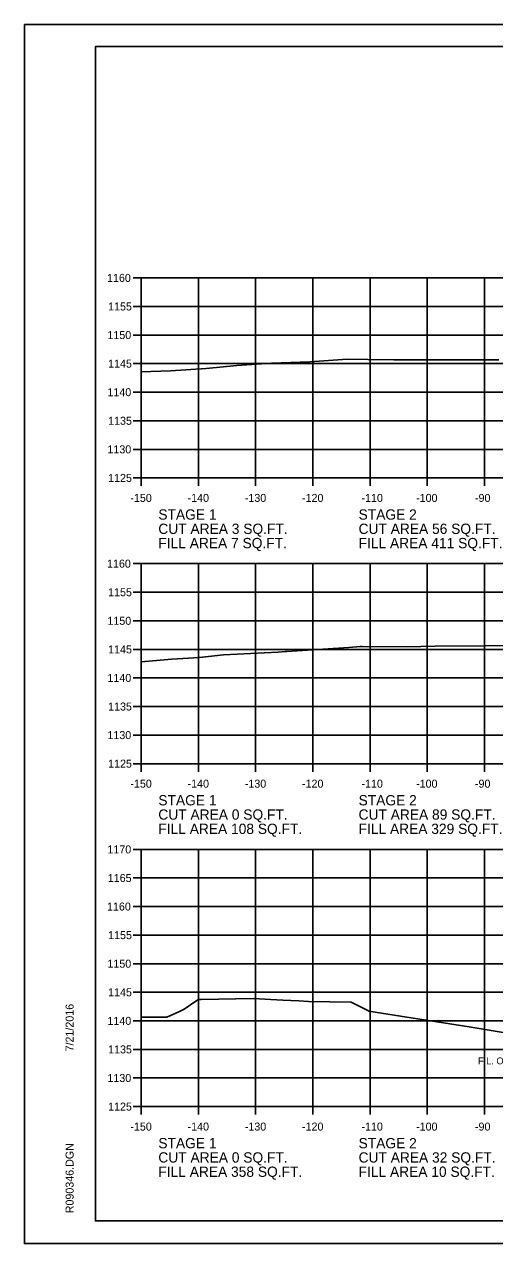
# Model space of a CAD drawing. Extents: x 1368971 to 1374497, y 378717 to 381839.
# Drawn here: x 1370882.3 to 1370964.5, y 379570.4 to 379783.8 of the extents above; entities that cross this region are included whole.
import ezdxf

# ---------------------------------------------------------------- set-up
doc = ezdxf.new("R2010")
doc.units = 0
for name, color, linetype in [('R_Axis', 7, 'Continuous'), ('R_Axis Annot', 7, 'Continuous'), ('R_Border', 7, 'Continuous'), ('R_Border Notes', 7, 'Continuous'), ('R_Exist Surface', 7, 'Continuous'), ('R_Grid', 7, 'Continuous'), ('R_No Plot', 7, 'Continuous')]:
    doc.layers.add(name, color=color, linetype=linetype)

msp = doc.modelspace()

# ---------------------------------------------------------------- linework, layer by layer
at = {"layer": 'R_Axis'}
for p, q in [((1370901.31, 379739.41), (1370902.71, 379739.41)), ((1370902.71, 379704.41), (1370902.71, 379739.41)), ((1370901.31, 379734.41), (1370902.71, 379734.41)), ((1370901.31, 379729.41), (1370902.71, 379729.41)), ((1370901.31, 379724.41), (1370902.71, 379724.41)), ((1370901.31, 379719.41), (1370902.71, 379719.41)), ((1370901.31, 379714.41), (1370902.71, 379714.41)), ((1370901.31, 379709.41), (1370902.71, 379709.41)), ((1370901.31, 379704.41), (1370902.71, 379704.41)), ((1370902.71, 379704.41), (1371202.71, 379704.41)), ((1370902.71, 379703.01), (1370902.71, 379704.41)), ((1370912.71, 379703.01), (1370912.71, 379704.41)), ((1370922.71, 379703.01), (1370922.71, 379704.41)), ((1370932.71, 379703.01), (1370932.71, 379704.41)), ((1370942.71, 379703.01), (1370942.71, 379704.41)), ((1370952.71, 379703.01), (1370952.71, 379704.41)), ((1370962.71, 379703.01), (1370962.71, 379704.41)), ((1370901.31, 379689.41), (1370902.71, 379689.41)), ((1370902.71, 379654.41), (1370902.71, 379689.41)), ((1370901.31, 379684.41), (1370902.71, 379684.41)), ((1370901.31, 379679.41), (1370902.71, 379679.41)), ((1370901.31, 379674.41), (1370902.71, 379674.41)), ((1370901.31, 379669.41), (1370902.71, 379669.41)), ((1370901.31, 379664.41), (1370902.71, 379664.41)), ((1370901.31, 379659.41), (1370902.71, 379659.41)), ((1370901.31, 379654.41), (1370902.71, 379654.41)), ((1370902.71, 379654.41), (1371202.71, 379654.41)), ((1370902.71, 379653.01), (1370902.71, 379654.41)), ((1370912.71, 379653.01), (1370912.71, 379654.41)), ((1370922.71, 379653.01), (1370922.71, 379654.41)), ((1370932.71, 379653.01), (1370932.71, 379654.41)), ((1370942.71, 379653.01), (1370942.71, 379654.41)), ((1370952.71, 379653.01), (1370952.71, 379654.41)), ((1370962.71, 379653.01), (1370962.71, 379654.41)), ((1370901.31, 379639.41), (1370902.71, 379639.41)), ((1370902.71, 379594.41), (1370902.71, 379639.41)), ((1370901.31, 379634.41), (1370902.71, 379634.41)), ((1370901.31, 379629.41), (1370902.71, 379629.41)), ((1370901.31, 379624.41), (1370902.71, 379624.41)), ((1370901.31, 379619.41), (1370902.71, 379619.41)), ((1370901.31, 379614.41), (1370902.71, 379614.41)), ((1370901.31, 379609.41), (1370902.71, 379609.41)), ((1370901.31, 379604.41), (1370902.71, 379604.41)), ((1370901.31, 379599.41), (1370902.71, 379599.41)), ((1370901.31, 379594.41), (1370902.71, 379594.41)), ((1370902.71, 379594.41), (1371202.71, 379594.41)), ((1370902.71, 379593.01), (1370902.71, 379594.41)), ((1370912.71, 379593.01), (1370912.71, 379594.41)), ((1370922.71, 379593.01), (1370922.71, 379594.41)), ((1370932.71, 379593.01), (1370932.71, 379594.41)), ((1370942.71, 379593.01), (1370942.71, 379594.41)), ((1370952.71, 379593.01), (1370952.71, 379594.41)), ((1370962.71, 379593.01), (1370962.71, 379594.41))]:
    msp.add_line(p, q, dxfattribs=at)
at = {"layer": 'R_Border'}
for p, q in [((1370894.71, 379779.87), (1371210.89, 379779.87)), ((1370894.71, 379574.41), (1370894.71, 379779.87)), ((1370894.71, 379574.41), (1370894.71, 379574.41)), ((1371210.89, 379574.41), (1370894.71, 379574.41))]:
    msp.add_line(p, q, dxfattribs=at)
at = {"layer": 'R_Exist Surface'}
for points in [[(1370902.71, 379722.95), (1370907.83, 379723.15), (1370914.06, 379723.56), (1370919.4, 379724.07), (1370925.49, 379724.49), (1370932.19, 379724.73), (1370938.7, 379725.2), (1370942.34, 379725.12), (1370946.87, 379725.09), (1370959.76, 379725.07), (1370962.04, 379725.08), (1370965.21, 379725.07)], [(1370902.71, 379672.21), (1370903.32, 379672.27), (1370908.07, 379672.67), (1370912.89, 379673), (1370917.1, 379673.46), (1370926.65, 379673.94), (1370927.86, 379674.03), (1370928.19, 379674.04), (1370930.85, 379674.23), (1370938.99, 379674.72), (1370940.96, 379674.92), (1370941.31, 379674.93), (1370949.06, 379674.88), (1370954.07, 379674.96), (1370962.9, 379675.03), (1370975.31, 379675.11)], [(1370902.71, 379610.03), (1370903.28, 379610.03), (1370907.17, 379610.04), (1370909.4, 379611.02), (1370910.2, 379611.43), (1370912.41, 379612.99), (1370912.72, 379613.14), (1370913.2, 379613.17), (1370922.31, 379613.32), (1370927.46, 379613.04), (1370930.27, 379612.9), (1370931.94, 379612.8), (1370939.41, 379612.67), (1370942.31, 379611.24), (1370942.48, 379611.11), (1370949.15, 379610.03), (1370960.06, 379608.36), (1370973.59, 379606.1)]]:
    msp.add_lwpolyline(points, dxfattribs=at)
at = {"layer": 'R_Grid'}
for p, q in [((1370902.71, 379739.41), (1371202.71, 379739.41)), ((1370902.71, 379704.41), (1370902.71, 379739.41)), ((1370912.71, 379704.41), (1370912.71, 379739.41)), ((1370922.71, 379704.41), (1370922.71, 379739.41)), ((1370932.71, 379704.41), (1370932.71, 379739.41)), ((1370942.71, 379704.41), (1370942.71, 379739.41)), ((1370952.71, 379704.41), (1370952.71, 379739.41)), ((1370962.71, 379704.41), (1370962.71, 379739.41)), ((1370902.71, 379734.41), (1371202.71, 379734.41)), ((1370902.71, 379729.41), (1371202.71, 379729.41)), ((1370902.71, 379724.41), (1371202.71, 379724.41)), ((1370902.71, 379719.41), (1371202.71, 379719.41)), ((1370902.71, 379714.41), (1371202.71, 379714.41)), ((1370902.71, 379709.41), (1371202.71, 379709.41)), ((1370902.71, 379704.41), (1371202.71, 379704.41)), ((1370902.71, 379689.41), (1371202.71, 379689.41)), ((1370902.71, 379654.41), (1370902.71, 379689.41)), ((1370912.71, 379654.41), (1370912.71, 379689.41)), ((1370922.71, 379654.41), (1370922.71, 379689.41)), ((1370932.71, 379654.41), (1370932.71, 379689.41)), ((1370942.71, 379654.41), (1370942.71, 379689.41)), ((1370952.71, 379654.41), (1370952.71, 379689.41)), ((1370962.71, 379654.41), (1370962.71, 379689.41)), ((1370902.71, 379684.41), (1371202.71, 379684.41)), ((1370902.71, 379679.41), (1371202.71, 379679.41)), ((1370902.71, 379674.41), (1371202.71, 379674.41)), ((1370902.71, 379669.41), (1371202.71, 379669.41)), ((1370902.71, 379664.41), (1371202.71, 379664.41)), ((1370902.71, 379659.41), (1371202.71, 379659.41)), ((1370902.71, 379654.41), (1371202.71, 379654.41)), ((1370902.71, 379639.41), (1371202.71, 379639.41)), ((1370902.71, 379594.41), (1370902.71, 379639.41)), ((1370912.71, 379594.41), (1370912.71, 379639.41)), ((1370922.71, 379594.41), (1370922.71, 379639.41)), ((1370932.71, 379594.41), (1370932.71, 379639.41)), ((1370942.71, 379594.41), (1370942.71, 379639.41)), ((1370952.71, 379594.41), (1370952.71, 379639.41)), ((1370962.71, 379594.41), (1370962.71, 379639.41)), ((1370902.71, 379634.41), (1371202.71, 379634.41)), ((1370902.71, 379629.41), (1371202.71, 379629.41)), ((1370902.71, 379624.41), (1371202.71, 379624.41)), ((1370902.71, 379619.41), (1371202.71, 379619.41)), ((1370902.71, 379614.41), (1371202.71, 379614.41)), ((1370902.71, 379609.41), (1371202.71, 379609.41)), ((1370902.71, 379604.41), (1371202.71, 379604.41)), ((1370902.71, 379599.41), (1371202.71, 379599.41)), ((1370902.71, 379594.41), (1371202.71, 379594.41))]:
    msp.add_line(p, q, dxfattribs=at)
at = {"layer": 'R_No Plot'}
for p, q in [((1370882.31, 379783.77), (1371215.64, 379783.77)), ((1370882.31, 379570.43), (1371215.64, 379570.43))]:
    msp.add_line(p, q, dxfattribs=at)
for points in [[(1370882.3, 379783.77), (1371215.64, 379783.77), (1371215.64, 379570.43), (1370882.3, 379570.43)], [(1371128.63, 379779.87), (1371128.63, 379769.99), (1371164.36, 379769.99), (1371164.36, 379767.07), (1371187.56, 379767.07), (1371187.56, 379742.74), (1371210.89, 379742.74), (1371210.89, 379574.41), (1370894.71, 379574.41), (1370894.71, 379779.87)]]:
    msp.add_lwpolyline(points, close=True, dxfattribs=at)

# ---------------------------------------------------------------- texts
at = {"layer": 'R_Axis'}
for p in [(1370902.71, 379704.41), (1370902.71, 379654.41), (1370902.71, 379594.41)]:
    msp.add_text('-', height=0.0001, dxfattribs=at).set_placement(p)
at = {"layer": 'R_Axis Annot'}
for s, height, p in [('1160', 1.4, (1370896.74, 379738.71)), ('1155', 1.4, (1370896.93, 379733.71)), ('1150', 1.4, (1370896.81, 379728.71)), ('1145', 1.4, (1370896.93, 379723.71)), ('1140', 1.4, (1370896.81, 379718.71)), ('1135', 1.4, (1370896.93, 379713.71)), ('1130', 1.4, (1370896.81, 379708.71)), ('1125', 1.4, (1370896.93, 379703.71)), ('-150', 1.4, (1370900.82, 379700.21)), ('-140', 1.4, (1370910.82, 379700.21)), ('-130', 1.4, (1370920.82, 379700.21)), ('-120', 1.4, (1370930.82, 379700.21)), ('-110', 1.4, (1370941.21, 379700.21)), ('-100', 1.4, (1370950.76, 379700.21)), ('-90', 1.4, (1370961.05, 379700.21)), ('STAGE 1', 1.8, (1370905.71, 379697.11)), ('STAGE 2', 1.8, (1370940.71, 379697.11)), ('CUT AREA 3 SQ.FT.', 1.8, (1370905.71, 379694.61)), ('CUT AREA 56 SQ.FT.', 1.8, (1370940.71, 379694.61)), ('FILL AREA 7 SQ.FT.', 1.8, (1370905.71, 379692.11)), ('FILL AREA 411 SQ.FT.', 1.8, (1370940.71, 379692.11)), ('1160', 1.4, (1370896.74, 379688.71)), ('1155', 1.4, (1370896.93, 379683.71)), ('1150', 1.4, (1370896.81, 379678.71)), ('1145', 1.4, (1370896.93, 379673.71)), ('1140', 1.4, (1370896.81, 379668.71)), ('1135', 1.4, (1370896.93, 379663.71)), ('1130', 1.4, (1370896.81, 379658.71)), ('1125', 1.4, (1370896.93, 379653.71)), ('-150', 1.4, (1370900.82, 379650.21)), ('-140', 1.4, (1370910.82, 379650.21)), ('-130', 1.4, (1370920.82, 379650.21)), ('-120', 1.4, (1370930.82, 379650.21)), ('-110', 1.4, (1370941.21, 379650.21)), ('-100', 1.4, (1370950.76, 379650.21)), ('-90', 1.4, (1370961.05, 379650.21)), ('STAGE 1', 1.8, (1370905.71, 379647.11)), ('STAGE 2', 1.8, (1370940.71, 379647.11)), ('CUT AREA 0 SQ.FT.', 1.8, (1370905.71, 379644.61)), ('CUT AREA 89 SQ.FT.', 1.8, (1370940.71, 379644.61)), ('FILL AREA 108 SQ.FT.', 1.8, (1370905.71, 379642.11)), ('FILL AREA 329 SQ.FT.', 1.8, (1370940.71, 379642.11)), ('1170', 1.4, (1370896.81, 379638.71)), ('1165', 1.4, (1370896.87, 379633.71)), ('1160', 1.4, (1370896.74, 379628.71)), ('1155', 1.4, (1370896.93, 379623.71)), ('1150', 1.4, (1370896.81, 379618.71)), ('1145', 1.4, (1370896.93, 379613.71)), ('1140', 1.4, (1370896.81, 379608.71)), ('1135', 1.4, (1370896.93, 379603.71)), ('1130', 1.4, (1370896.81, 379598.71)), ('1125', 1.4, (1370896.93, 379593.71)), ('-150', 1.4, (1370900.82, 379590.21)), ('-140', 1.4, (1370910.82, 379590.21)), ('-130', 1.4, (1370920.82, 379590.21)), ('-120', 1.4, (1370930.82, 379590.21)), ('-110', 1.4, (1370941.21, 379590.21)), ('-100', 1.4, (1370950.76, 379590.21)), ('-90', 1.4, (1370961.05, 379590.21)), ('STAGE 1', 1.8, (1370905.71, 379587.11)), ('STAGE 2', 1.8, (1370940.71, 379587.11)), ('CUT AREA 0 SQ.FT.', 1.8, (1370905.71, 379584.61)), ('CUT AREA 32 SQ.FT.', 1.8, (1370940.71, 379584.61)), ('FILL AREA 358 SQ.FT.', 1.8, (1370905.71, 379582.11)), ('FILL AREA 10 SQ.FT.', 1.8, (1370940.71, 379582.11))]:
    msp.add_text(s, height=height, dxfattribs=at).set_placement(p)
at = {"layer": 'R_Border'}
for s, p in [('7/21/2016', (1370890.9, 379604.06)), ('R090346.DGN', (1370890.9, 379575.74))]:
    msp.add_text(s, height=1.4, rotation=90, dxfattribs=at).set_placement(p)
at = {"layer": 'R_Border Notes'}
msp.add_text('F.L. OUTLET (LT.)=1136.45', height=1.2, dxfattribs=at).set_placement((1370961.59, 379601.81))

doc.saveas('drawing.dxf')
